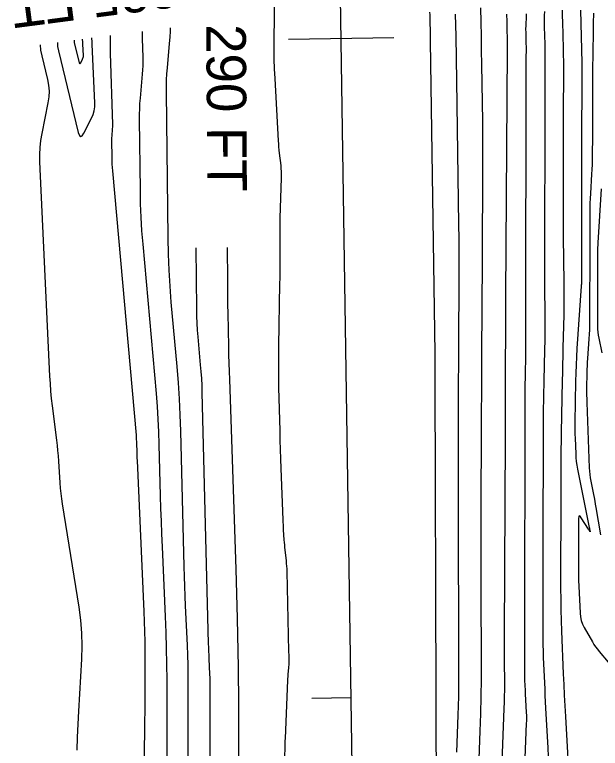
# Model space of a CAD drawing. Extents: x 1768942 to 1774819, y 723037 to 732099.
# Drawn here: x 1770772.9 to 1770861.8, y 724629.5 to 724740.8 of the extents above; entities that cross this region are included whole.
import ezdxf

# ---------------------------------------------------------------- set-up
doc = ezdxf.new("R2010")
doc.units = 0
for name, color, linetype in [('R_Contour Annot', 7, 'Continuous'), ('R_Contours', 7, 'Continuous'), ('R_Horz Alg', 7, 'Continuous')]:
    doc.layers.add(name, color=color, linetype=linetype)

msp = doc.modelspace()

# ---------------------------------------------------------------- linework, layer by layer
at = {"layer": 'R_Contours'}
for points in [[(1770813.9, 724628.27), (1770813.93, 724629.66), (1770813.94, 724630), (1770813.95, 724630.35), (1770813.96, 724630.7), (1770813.97, 724631.04), (1770814.36, 724639.91), (1770814.37, 724640.14), (1770814.39, 724640.37), (1770814.4, 724640.6), (1770814.42, 724640.82), (1770814.5, 724641.77), (1770814.52, 724641.98), (1770814.53, 724642.18), (1770814.53, 724642.39), (1770814.53, 724642.59), (1770814.53, 724643.41), (1770814.53, 724643.61), (1770814.53, 724643.82), (1770814.52, 724644.02), (1770814.52, 724644.23), (1770814.24, 724656.37), (1770814.23, 724656.78), (1770814.21, 724657.18), (1770814.17, 724657.58), (1770814.13, 724657.98), (1770813.94, 724659.64), (1770813.9, 724660.02), (1770813.87, 724660.4), (1770813.84, 724660.78), (1770813.81, 724661.16), (1770813.71, 724662.68), (1770813.69, 724663.07), (1770813.67, 724663.45), (1770813.65, 724663.83), (1770813.64, 724664.21), (1770813.34, 724672.01), (1770813.28, 724673.44), (1770813.24, 724674.87), (1770813.19, 724676.29), (1770813.16, 724677.72), (1770813, 724684.27), (1770812.97, 724685.83), (1770812.96, 724687.4), (1770812.96, 724688.97), (1770812.98, 724690.54), (1770813.15, 724700.05), (1770813.16, 724700.87), (1770813.17, 724701.7), (1770813.17, 724702.52), (1770813.17, 724703.35), (1770813.16, 724706.65), (1770813.16, 724707.48), (1770813.17, 724708.3), (1770813.18, 724709.13), (1770813.2, 724709.96), (1770813.4, 724716.09), (1770813.4, 724716.56), (1770813.39, 724717.03), (1770813.36, 724717.49), (1770813.32, 724717.96), (1770813.1, 724719.83), (1770813.05, 724720.29), (1770813, 724720.76), (1770812.97, 724721.23), (1770812.94, 724721.7), (1770812.4, 724731.13), (1770812.33, 724732.61), (1770812.29, 724734.1), (1770812.27, 724735.58), (1770812.28, 724737.07), (1770812.37, 724743.93)], [(1770843.13, 724620.91), (1770843.55, 724632.15), (1770843.64, 724634.79), (1770843.69, 724637.42), (1770843.73, 724640.06), (1770843.73, 724642.69), (1770843.7, 724653.23), (1770843.69, 724655.86), (1770843.69, 724658.5), (1770843.69, 724661.13), (1770843.7, 724663.77), (1770843.76, 724680.19), (1770843.77, 724683.81), (1770843.79, 724687.42), (1770843.81, 724691.04), (1770843.83, 724694.65), (1770843.96, 724716.03), (1770843.97, 724718.18), (1770843.97, 724720.33), (1770843.95, 724722.49), (1770843.92, 724724.64), (1770843.79, 724733.25), (1770843.76, 724735.41), (1770843.73, 724737.56), (1770843.69, 724739.71), (1770843.65, 724741.86)], [(1770853.28, 724741.3), (1770853.26, 724740.73), (1770853.25, 724740.15), (1770853.25, 724739.57), (1770853.26, 724739), (1770853.34, 724736.34), (1770853.35, 724735.7), (1770853.36, 724735.07), (1770853.37, 724734.43), (1770853.36, 724733.8), (1770853.34, 724730.13), (1770853.34, 724729.3), (1770853.34, 724728.48), (1770853.33, 724727.66), (1770853.33, 724726.83), (1770853.29, 724703.38), (1770853.29, 724702.43), (1770853.29, 724701.47), (1770853.3, 724700.51), (1770853.31, 724699.56), (1770853.37, 724695.37), (1770853.38, 724694.6), (1770853.38, 724693.83), (1770853.37, 724693.06), (1770853.36, 724692.28), (1770853.29, 724689.2), (1770853.27, 724688.43), (1770853.25, 724687.66), (1770853.23, 724686.88), (1770853.22, 724686.11), (1770853.13, 724682.16), (1770853.11, 724681.24), (1770853.1, 724680.32), (1770853.09, 724679.41), (1770853.09, 724678.49), (1770853.07, 724659.5), (1770853.07, 724658.07), (1770853.06, 724656.65), (1770853.06, 724655.22), (1770853.06, 724653.79), (1770853.04, 724647.16), (1770853.04, 724646.2), (1770853.06, 724645.24), (1770853.08, 724644.28), (1770853.12, 724643.32), (1770853.29, 724639.48), (1770853.33, 724638.52), (1770853.38, 724637.56), (1770853.43, 724636.6), (1770853.48, 724635.64), (1770853.82, 724629.63), (1770853.88, 724628.31)], [(1770856.01, 724741.51), (1770856.01, 724740.63), (1770856.03, 724739.75), (1770856.14, 724735.69), (1770856.16, 724734.72), (1770856.18, 724733.75), (1770856.18, 724732.78), (1770856.18, 724731.81), (1770856.15, 724726.21), (1770856.14, 724724.95), (1770856.14, 724723.7), (1770856.13, 724722.44), (1770856.13, 724721.18), (1770856.12, 724713.27), (1770856.12, 724711.72), (1770856.12, 724710.17), (1770856.13, 724708.62), (1770856.15, 724707.07), (1770856.25, 724700.28), (1770856.26, 724699.03), (1770856.26, 724697.78), (1770856.25, 724696.53), (1770856.23, 724695.28), (1770856.11, 724690.28), (1770856.08, 724689.03), (1770856.06, 724687.78), (1770856.03, 724686.53), (1770856, 724685.28), (1770855.83, 724677.43), (1770855.82, 724676.67), (1770855.81, 724675.9), (1770855.8, 724675.13), (1770855.8, 724674.36), (1770855.79, 724671.28), (1770855.79, 724670.51), (1770855.79, 724669.75), (1770855.79, 724668.98), (1770855.79, 724668.21), (1770855.75, 724653.78), (1770855.76, 724652.17), (1770855.78, 724650.55), (1770855.82, 724648.93), (1770855.88, 724647.32), (1770856.16, 724640.86), (1770856.24, 724639.24), (1770856.31, 724637.62), (1770856.4, 724636.01), (1770856.49, 724634.4), (1770857.17, 724622.43)], [(1770858.77, 724741.5), (1770858.99, 724733.53), (1770858.99, 724733.43), (1770858.99, 724733.32), (1770858.99, 724733.21), (1770858.99, 724733.11), (1770858.98, 724732.68), (1770858.98, 724732.57), (1770858.98, 724732.47), (1770858.98, 724732.36), (1770858.98, 724732.25), (1770858.94, 724720.48), (1770858.94, 724720.33), (1770858.94, 724720.17), (1770858.94, 724720.01), (1770858.94, 724719.86), (1770858.94, 724718.92), (1770858.94, 724718.88), (1770858.94, 724718.86), (1770858.94, 724718.65), (1770858.94, 724718.61), (1770858.94, 724718.58), (1770858.94, 724718.54), (1770858.94, 724718.5), (1770858.91, 724701.53), (1770858.91, 724701.37), (1770858.91, 724701.21), (1770858.91, 724701.06), (1770858.91, 724700.9), (1770858.91, 724700.27), (1770858.9, 724700.11), (1770858.9, 724699.95), (1770858.89, 724699.8), (1770858.88, 724699.64), (1770858.23, 724690.18), (1770858.16, 724688.94), (1770858.1, 724687.7), (1770858.05, 724686.47), (1770858.03, 724685.23), (1770857.92, 724678.98), (1770857.92, 724678.38), (1770857.92, 724677.79), (1770857.93, 724677.2), (1770857.95, 724676.61), (1770858.04, 724674.24), (1770858.07, 724673.65), (1770858.13, 724673.06), (1770858.21, 724672.48), (1770858.31, 724671.9), (1770860.09, 724663.06), (1770860.1, 724663.04), (1770860.1, 724663.02), (1770860.1, 724663), (1770860.11, 724662.99), (1770860.12, 724662.91), (1770860.12, 724662.89), (1770860.13, 724662.88), (1770860.13, 724662.86), (1770860.13, 724662.84), (1770860.24, 724662.42), (1770860.25, 724662.38), (1770860.25, 724662.37), (1770860.24, 724662.38), (1770860.22, 724662.42), (1770860.11, 724662.61), (1770860.09, 724662.66), (1770860.06, 724662.71), (1770860.03, 724662.75), (1770860, 724662.8), (1770858.87, 724664.53), (1770858.7, 724664.75), (1770858.57, 724664.81), (1770858.5, 724664.69), (1770858.47, 724664.41), (1770858.45, 724657.6), (1770858.46, 724656.73), (1770858.47, 724655.86), (1770858.49, 724654.99), (1770858.53, 724654.12), (1770858.7, 724650.03), (1770858.76, 724649.47), (1770858.88, 724648.92), (1770859.07, 724648.4), (1770859.32, 724647.89), (1770860.57, 724645.71), (1770860.81, 724645.32), (1770861.06, 724644.94), (1770861.33, 724644.57), (1770861.62, 724644.22), (1770862.99, 724642.61)], [(1770835.87, 724741.19), (1770835.88, 724740.82), (1770835.89, 724740.46), (1770835.9, 724740.1), (1770835.91, 724739.73), (1770835.94, 724738.27), (1770835.94, 724737.91), (1770835.95, 724737.55), (1770835.95, 724737.18), (1770835.96, 724736.82), (1770836.67, 724689.45), (1770836.67, 724689.24), (1770836.68, 724689.03), (1770836.68, 724688.82), (1770836.68, 724688.62), (1770836.67, 724687.74), (1770836.67, 724687.56), (1770836.67, 724687.37), (1770836.67, 724687.19), (1770836.67, 724687.01), (1770836.66, 724686.28), (1770836.66, 724686.1), (1770836.66, 724685.91), (1770836.66, 724685.73), (1770836.66, 724685.55), (1770836.81, 724637.51), (1770836.81, 724637.44), (1770836.81, 724637.37), (1770836.81, 724637.3), (1770836.8, 724637.23), (1770836.79, 724636.96), (1770836.79, 724636.89), (1770836.79, 724636.82), (1770836.79, 724636.75), (1770836.79, 724636.68), (1770836.95, 724590.56)], [(1770839.77, 724740.93), (1770839.83, 724737.55), (1770839.89, 724734.17), (1770839.94, 724730.79), (1770840.27, 724709), (1770840.3, 724706.84), (1770840.31, 724704.68), (1770840.31, 724702.52), (1770840.31, 724700.36), (1770840.25, 724691.19), (1770840.24, 724689.3), (1770840.23, 724687.4), (1770840.22, 724685.5), (1770840.21, 724683.6), (1770840.19, 724676), (1770840.18, 724674.1), (1770840.18, 724672.21), (1770840.18, 724670.31), (1770840.18, 724668.41), (1770840.27, 724640.22), (1770840.27, 724638.81), (1770840.25, 724637.4), (1770840.22, 724635.99), (1770840.17, 724634.58), (1770839.96, 724628.94)], [(1770847.54, 724740.9), (1770847.56, 724740.53), (1770847.57, 724740.16), (1770847.58, 724739.79), (1770847.61, 724737.96), (1770847.62, 724737.76), (1770847.62, 724737.56), (1770847.62, 724737.37), (1770847.63, 724737.17), (1770847.64, 724736.38), (1770847.64, 724736.18), (1770847.64, 724735.98), (1770847.64, 724735.79), (1770847.64, 724735.59), (1770847.41, 724698.11), (1770847.38, 724692.78), (1770847.35, 724687.45), (1770847.33, 724682.11), (1770847.31, 724676.78), (1770847.2, 724646.63), (1770847.2, 724645.71), (1770847.2, 724644.79), (1770847.2, 724643.87), (1770847.2, 724642.95), (1770847.21, 724639.28), (1770847.21, 724638.36), (1770847.2, 724637.44), (1770847.18, 724636.53), (1770847.15, 724635.61), (1770846.14, 724608.57)], [(1770849.86, 724615.06), (1770850.59, 724633.3), (1770850.61, 724633.72), (1770850.61, 724634.14), (1770850.6, 724634.55), (1770850.58, 724634.97), (1770850.47, 724636.88), (1770850.45, 724637.18), (1770850.44, 724637.49), (1770850.42, 724637.79), (1770850.41, 724638.1), (1770850.36, 724639.32), (1770850.34, 724639.62), (1770850.34, 724639.93), (1770850.33, 724640.23), (1770850.33, 724640.54), (1770850.34, 724642.64), (1770850.34, 724643.1), (1770850.34, 724643.55), (1770850.34, 724644), (1770850.34, 724644.45), (1770850.38, 724684.06), (1770850.38, 724684.4), (1770850.39, 724684.75), (1770850.39, 724685.1), (1770850.4, 724685.45), (1770850.43, 724686.95), (1770850.44, 724687.24), (1770850.44, 724687.53), (1770850.45, 724687.82), (1770850.46, 724688.12), (1770850.48, 724689.29), (1770850.49, 724689.58), (1770850.49, 724689.87), (1770850.49, 724690.16), (1770850.49, 724690.46), (1770850.47, 724692.05), (1770850.46, 724692.41), (1770850.46, 724692.77), (1770850.46, 724693.13), (1770850.46, 724693.49), (1770850.53, 724732.48), (1770850.53, 724732.87), (1770850.53, 724733.26), (1770850.53, 724733.65), (1770850.54, 724734.04), (1770850.55, 724735.78), (1770850.55, 724736.08), (1770850.54, 724736.38), (1770850.54, 724736.68), (1770850.53, 724736.98), (1770850.5, 724738.24), (1770850.49, 724738.52), (1770850.49, 724738.79), (1770850.5, 724739.06), (1770850.51, 724739.34), (1770850.56, 724740.43), (1770850.56, 724740.7), (1770850.56, 724740.97)], [(1770860.76, 724741.04), (1770860.73, 724740.55), (1770860.71, 724740.06), (1770860.7, 724739.56), (1770860.69, 724739.07), (1770860.63, 724734.21), (1770860.61, 724733.24), (1770860.61, 724732.27), (1770860.6, 724731.29), (1770860.6, 724730.32), (1770860.58, 724725.31), (1770860.58, 724724.58), (1770860.58, 724723.86), (1770860.57, 724723.14), (1770860.57, 724722.42), (1770860.56, 724719.54), (1770860.55, 724718.81), (1770860.53, 724718.09), (1770860.5, 724717.37), (1770860.46, 724716.65), (1770860.27, 724713.69), (1770860.23, 724712.96), (1770860.2, 724712.23), (1770860.18, 724711.49), (1770860.18, 724710.76), (1770860.16, 724704.22), (1770860.16, 724703.1), (1770860.16, 724701.99), (1770860.16, 724700.87), (1770860.15, 724699.75), (1770860.14, 724694.41), (1770860.13, 724693.73), (1770860.11, 724693.04), (1770860.08, 724692.35), (1770860.04, 724691.67), (1770859.83, 724688.66), (1770859.8, 724688.1), (1770859.77, 724687.55), (1770859.75, 724686.99), (1770859.74, 724686.44), (1770859.7, 724684.22), (1770859.7, 724683.66), (1770859.7, 724683.11), (1770859.71, 724682.55), (1770859.73, 724682), (1770860.09, 724672.1), (1770860.12, 724671.59), (1770860.17, 724671.08), (1770860.24, 724670.58), (1770860.33, 724670.07), (1770860.73, 724668.07), (1770860.83, 724667.57), (1770860.93, 724667.06), (1770861.02, 724666.56), (1770861.11, 724666.06), (1770861.8, 724661.94)], [(1770792.24, 724738.3), (1770792.24, 724738.13), (1770792.24, 724737.66), (1770792.24, 724737.2), (1770792.33, 724734.35), (1770792.34, 724733.72), (1770792.33, 724733.09), (1770792.3, 724732.46), (1770792.25, 724731.83), (1770791.92, 724728.19), (1770791.85, 724727.37), (1770791.81, 724726.56), (1770791.79, 724725.74), (1770791.79, 724724.92), (1770791.91, 724714.22), (1770791.95, 724712.16), (1770792.04, 724710.11), (1770792.16, 724708.06), (1770792.32, 724706.01), (1770794.35, 724683.35), (1770794.5, 724681.42), (1770794.63, 724679.49), (1770794.73, 724677.55), (1770794.79, 724675.62), (1770794.99, 724667.87), (1770795.04, 724665.94), (1770795.11, 724664), (1770795.18, 724662.07), (1770795.26, 724660.13), (1770795.74, 724649.55), (1770795.84, 724647.14), (1770795.9, 724644.73), (1770795.95, 724642.32), (1770795.96, 724639.91), (1770795.97, 724615.46)], [(1770799.24, 724627.33), (1770799.24, 724639.21), (1770799.23, 724640.7), (1770799.21, 724642.19), (1770799.16, 724643.69), (1770799.1, 724645.18), (1770798.84, 724651.15), (1770798.77, 724652.65), (1770798.72, 724654.14), (1770798.67, 724655.63), (1770798.62, 724657.13), (1770798.1, 724677.67), (1770798.02, 724680.12), (1770797.89, 724682.56), (1770797.73, 724685.01), (1770797.54, 724687.44), (1770796.66, 724697.2), (1770796.47, 724699.64), (1770796.32, 724702.08), (1770796.22, 724704.52), (1770796.17, 724706.97), (1770795.92, 724729.08), (1770795.92, 724730.01), (1770795.94, 724730.94), (1770795.99, 724731.86), (1770796.07, 724732.79), (1770796.41, 724736.48), (1770796.48, 724737.41), (1770796.52, 724738.33), (1770796.54, 724738.86)], [(1770779.37, 724736.61), (1770779.41, 724736.01), (1770779.53, 724735.37), (1770782.54, 724722.96), (1770782.71, 724722.5), (1770782.91, 724722.33), (1770783.14, 724722.45), (1770783.4, 724722.86), (1770784.53, 724725.11), (1770784.78, 724725.68), (1770784.94, 724726.26), (1770785.03, 724726.86), (1770785.04, 724727.48), (1770784.65, 724736.32), (1770784.63, 724736.77), (1770784.6, 724737.22), (1770784.6, 724737.3)], [(1770781.91, 724736.95), (1770781.9, 724736.92), (1770781.92, 724736.77), (1770781.94, 724736.61), (1770782.69, 724733.53), (1770782.73, 724733.42), (1770782.78, 724733.38), (1770782.84, 724733.41), (1770782.91, 724733.51), (1770783.18, 724734.07), (1770783.25, 724734.21), (1770783.29, 724734.35), (1770783.31, 724734.5), (1770783.31, 724734.65), (1770783.23, 724736.38), (1770783.22, 724736.72), (1770783.2, 724737.06), (1770783.2, 724737.11)], [(1770792.38, 724618.38), (1770792.63, 724632.17), (1770792.65, 724633.68), (1770792.67, 724635.19), (1770792.68, 724636.7), (1770792.68, 724638.21), (1770792.68, 724644.25), (1770792.67, 724645.75), (1770792.64, 724647.26), (1770792.6, 724648.77), (1770792.54, 724650.28), (1770791.51, 724673.23), (1770791.49, 724673.54), (1770791.48, 724673.86), (1770791.47, 724674.18), (1770791.46, 724674.5), (1770791.43, 724675.77), (1770791.42, 724676.09), (1770791.4, 724676.41), (1770791.38, 724676.73), (1770791.36, 724677.05), (1770787.77, 724717.14), (1770787.73, 724717.64), (1770787.7, 724718.14), (1770787.68, 724718.65), (1770787.67, 724719.15), (1770787.64, 724721.77), (1770787.64, 724721.97), (1770787.65, 724722.18), (1770787.66, 724722.38), (1770787.67, 724722.58), (1770787.75, 724723.38), (1770787.76, 724723.58), (1770787.77, 724723.78), (1770787.77, 724723.98), (1770787.77, 724724.18), (1770787.45, 724734.99), (1770787.43, 724736.26), (1770787.43, 724737.54), (1770787.43, 724737.67)], [(1770776.78, 724736.28), (1770776.83, 724735.47), (1770777, 724734.58), (1770777.86, 724731.02), (1770778.03, 724730.13), (1770778.1, 724729.24), (1770778.07, 724728.35), (1770777.94, 724727.45), (1770777.01, 724722.83), (1770776.82, 724721.76), (1770776.71, 724720.68), (1770776.66, 724719.6), (1770776.68, 724718.51), (1770778.19, 724686.01), (1770778.25, 724684.88), (1770778.34, 724683.74), (1770778.44, 724682.61), (1770778.58, 724681.48), (1770779.23, 724676.31), (1770779.32, 724675.5), (1770779.41, 724674.7), (1770779.47, 724673.89), (1770779.53, 724673.08), (1770779.73, 724669.83), (1770779.79, 724669.02), (1770779.87, 724668.22), (1770779.97, 724667.41), (1770780.09, 724666.61), (1770782.64, 724650.95), (1770782.9, 724649), (1770783.05, 724647.03), (1770783.1, 724645.07), (1770783.04, 724643.09), (1770782.57, 724635.19), (1770782.46, 724633.21), (1770782.37, 724631.23), (1770782.31, 724629.25)], [(1770862.07, 724689.56), (1770861.59, 724691.74), (1770861.5, 724692.2), (1770861.43, 724692.66), (1770861.4, 724693.13), (1770861.38, 724693.6), (1770861.41, 724702.06), (1770861.41, 724702.41), (1770861.41, 724702.76), (1770861.41, 724703.11), (1770861.41, 724703.45), (1770861.41, 724704.85), (1770861.42, 724705.19), (1770861.42, 724705.54), (1770861.44, 724705.89), (1770861.46, 724706.24), (1770861.98, 724714.4)], [(1770800.37, 724705.47), (1770800.48, 724696.15), (1770800.5, 724695.09), (1770800.54, 724694.04), (1770800.61, 724692.99), (1770800.69, 724691.94), (1770801.06, 724687.74), (1770801.15, 724686.7), (1770801.22, 724685.64), (1770801.27, 724684.59), (1770801.31, 724683.54), (1770802.28, 724645.43), (1770802.3, 724644.85), (1770802.32, 724644.28), (1770802.34, 724643.7), (1770802.36, 724643.12), (1770802.47, 724640.81), (1770802.49, 724640.24), (1770802.51, 724639.66), (1770802.52, 724639.08), (1770802.52, 724638.5), (1770802.52, 724633.92), (1770802.52, 724632.96), (1770802.52, 724632), (1770802.53, 724631.04), (1770802.53, 724630.09), (1770802.68, 724593.34)], [(1770806.94, 724606.63), (1770806.91, 724634.33), (1770806.9, 724636.19), (1770806.89, 724638.06), (1770806.87, 724639.92), (1770806.84, 724641.79), (1770806.71, 724649.25), (1770806.68, 724651.12), (1770806.63, 724652.98), (1770806.58, 724654.85), (1770806.52, 724656.71), (1770805.52, 724685.47), (1770805.48, 724686.73), (1770805.44, 724687.99), (1770805.41, 724689.25), (1770805.38, 724690.51), (1770805.28, 724695.55), (1770805.25, 724696.8), (1770805.24, 724698.06), (1770805.22, 724699.32), (1770805.22, 724700.58), (1770805.2, 724705.5)]]:
    msp.add_lwpolyline(points, dxfattribs=at)
at = {"layer": 'R_Horz Alg'}
msp.add_line((1770830.14, 724237.3), (1770821.12, 724822.68), dxfattribs=at)
msp.add_line((1770830.14, 724237.3), (1770821.12, 724822.68), dxfattribs=at)
for points in [[(1770814.43, 724737.12), (1770830.43, 724737.36)], [(1770817.98, 724637.16), (1770823.97, 724637.25)]]:
    msp.add_lwpolyline(points, dxfattribs=at)

# ---------------------------------------------------------------- texts
at = {"layer": 'R_Contour Annot'}
for s, rotation, p in [('285 FT', 187.45, (1770797.21, 724748.02)), ('290 FT', 270.3874, (1770801.97, 724739.38))]:
    msp.add_text(s, height=6, rotation=rotation, dxfattribs=at).set_placement(p)

doc.saveas('drawing.dxf')
